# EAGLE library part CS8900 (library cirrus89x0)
Cirrus Logic CS8900 ethernet controller (100-pin TQFP package)
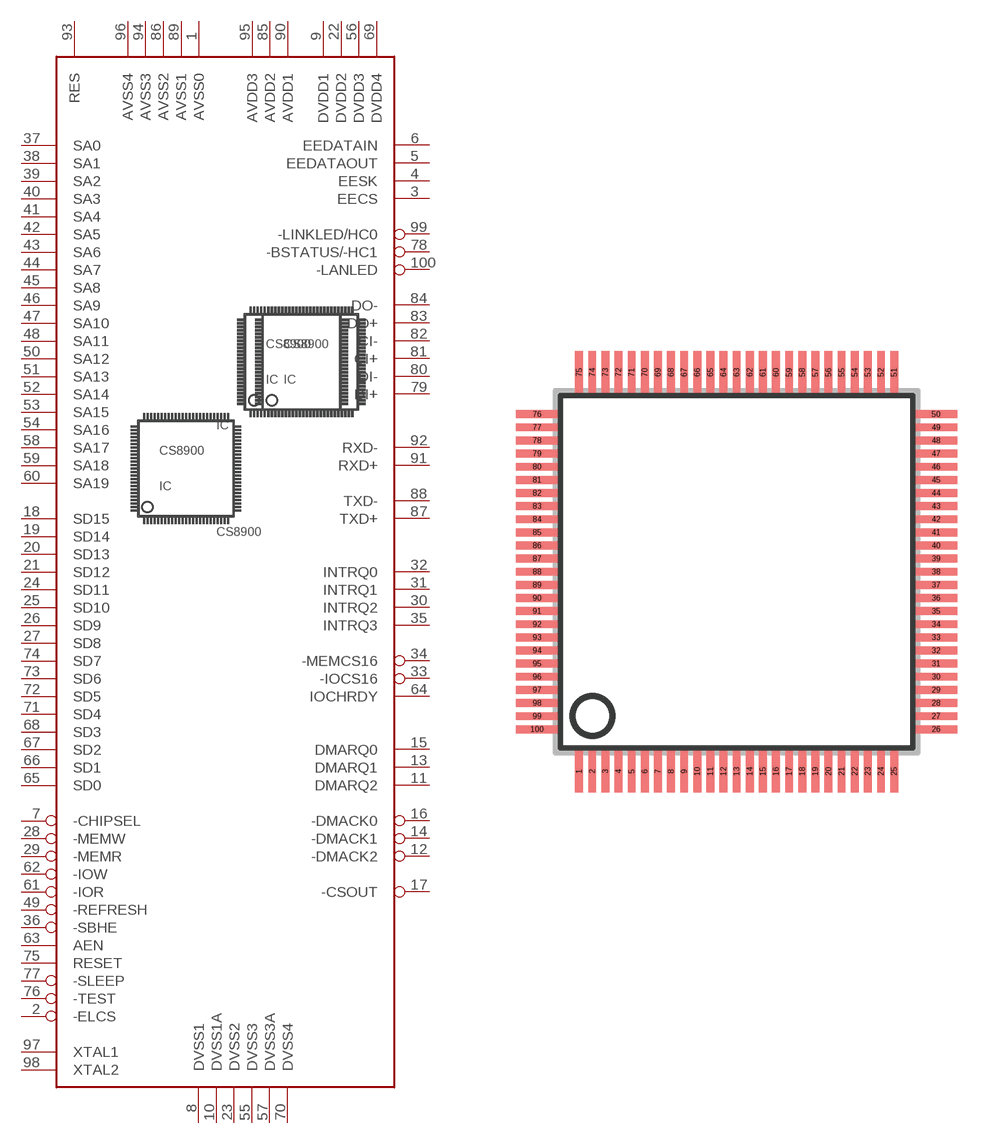
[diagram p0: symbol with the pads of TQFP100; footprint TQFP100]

Designator prefix IC

## CS8900  [TQFP100]
1  AVSS0  pwr
2  -ELCS
3  EECS  out
4  EESK  out
5  EEDATAOUT  out
6  EEDATAIN  in
7  -CHIPSEL  in
8  DVSS1  pwr
9  DVDD1  pwr
10  DVSS1A  pwr
11  DMARQ2  hiz
12  -DMACK2  in
13  DMARQ1  hiz
14  -DMACK1  in
15  DMARQ0  hiz
16  -DMACK0  in
17  -CSOUT  out
18  SD15
19  SD14
20  SD13
21  SD12
22  DVDD2  pwr
23  DVSS2  pwr
24  SD11
25  SD10
26  SD9
27  SD8
28  -MEMW  in
29  -MEMR  in
30  INTRQ2  hiz
31  INTRQ1  hiz
32  INTRQ0  hiz
33  -IOCS16  oc
34  -MEMCS16  oc
35  INTRQ3  hiz
36  -SBHE  in
37  SA0  in
38  SA1  in
39  SA2  in
40  SA3  in
41  SA4  in
42  SA5  in
43  SA6  in
44  SA7  in
45  SA8  in
46  SA9  in
47  SA10  in
48  SA11  in
49  -REFRESH  in
50  SA12  in
51  SA13  pwr
52  SA14  pwr
53  SA15  pwr
54  SA16  in
55  DVSS3  pwr
56  DVDD3  pwr
57  DVSS3A  pwr
58  SA17  in
59  SA18  in
60  SA19  in
61  -IOR  in
62  -IOW  in
63  AEN  in
64  IOCHRDY  oc
65  SD0
66  SD1
67  SD2
68  SD3
69  DVDD4  pwr
70  DVSS4  pwr
71  SD4
72  SD5
73  SD6
74  SD7
75  RESET  in
76  -TEST  in
77  -SLEEP  in
78  -BSTATUS/-HC1  oc
79  DI+  in
80  DI-  in
81  CI+  in
82  CI-  in
83  DO+  out
84  DO-  out
85  AVDD2  pwr
86  AVSS2  pwr
87  TXD+  out
88  TXD-  out
89  AVSS1  pwr
90  AVDD1  pwr
91  RXD+  in
92  RXD-  in
93  RES  in
94  AVSS3  pwr
95  AVDD3  pwr
96  AVSS4  pwr
97  XTAL1  pas
98  XTAL2  pas
99  -LINKLED/HC0  oc
100  -LANLED  oc

## Footprint TQFP100 (pad centres in mm)
smd 0.3 x 1.6: 1 -6.2,-7.6; 2 -5.7,-7.6; 3 -5.2,-7.6; 4 -4.7,-7.6; 5 -4.2,-7.6; 6 -3.7,-7.6; 7 -3.2,-7.6; 8 -2.7,-7.6; 9 -2.2,-7.6; 10 -1.7,-7.6; 11 -1.2,-7.6; 12 -0.7,-7.6; 13 -0.2,-7.6; 14 0.3,-7.6; 15 0.8,-7.6; 16 1.3,-7.6; 17 1.8,-7.6; 18 2.3,-7.6; 19 2.8,-7.6; 20 3.3,-7.6; 21 3.8,-7.6; 22 4.3,-7.6; 23 4.8,-7.6; 24 5.3,-7.6; 25 5.8,-7.6; 51 5.8,7.6; 52 5.3,7.6; 53 4.8,7.6; 54 4.3,7.6; 55 3.8,7.6; 56 3.3,7.6; 57 2.8,7.6; 58 2.3,7.6; 59 1.8,7.6; 60 1.3,7.6; 61 0.8,7.6; 62 0.3,7.6; 63 -0.2,7.6; 64 -0.7,7.6; 65 -1.2,7.6; 66 -1.7,7.6; 67 -2.2,7.6; 68 -2.7,7.6; 69 -3.2,7.6; 70 -3.7,7.6; 71 -4.2,7.6; 72 -4.7,7.6; 73 -5.2,7.6; 74 -5.7,7.6; 75 -6.2,7.6
smd 1.6 x 0.3: 26 7.4,-6; 27 7.4,-5.5; 28 7.4,-5; 29 7.4,-4.5; 30 7.4,-4; 31 7.4,-3.5; 32 7.4,-3; 33 7.4,-2.5; 34 7.4,-2; 35 7.4,-1.5; 36 7.4,-1; 37 7.4,-0.5; 38 7.4,0; 39 7.4,0.5; 40 7.4,1; 41 7.4,1.5; 42 7.4,2; 43 7.4,2.5; 44 7.4,3; 45 7.4,3.5; 46 7.4,4; 47 7.4,4.5; 48 7.4,5; 49 7.4,5.5; 50 7.4,6; 76 -7.8,6; 77 -7.8,5.5; 78 -7.8,5; 79 -7.8,4.5; 80 -7.8,4; 81 -7.8,3.5; 82 -7.8,3; 83 -7.8,2.5; 84 -7.8,2; 85 -7.8,1.5; 86 -7.8,1; 87 -7.8,0.5; 88 -7.8,0; 89 -7.8,-0.5; 90 -7.8,-1; 91 -7.8,-1.5; 92 -7.8,-2; 93 -7.8,-2.5; 94 -7.8,-3; 95 -7.8,-3.5; 96 -7.8,-4; 97 -7.8,-4.5; 98 -7.8,-5; 99 -7.8,-5.5; 100 -7.8,-6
